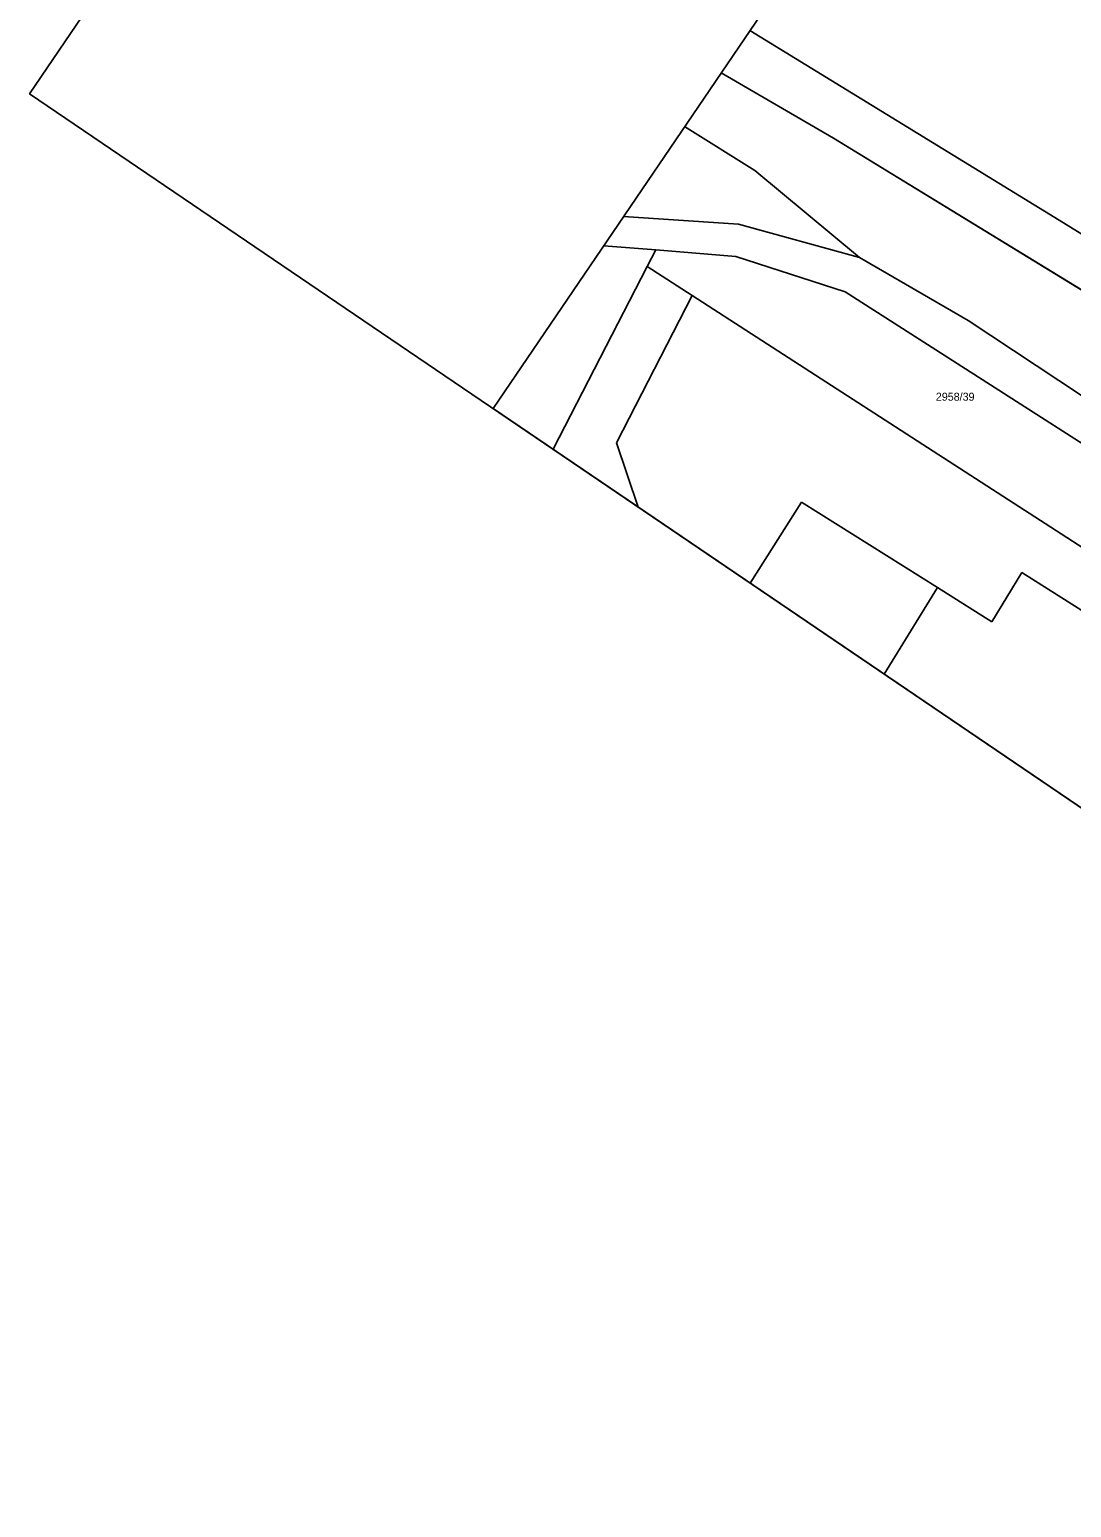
# Model space of a CAD drawing. Extents: x -621058 to -620110, y -1122807 to -1122030.
# Drawn here: x -621058.1 to -620862.9, y -1122540.7 to -1122263.7 of the extents above; entities that cross this region are included whole.
import ezdxf

# ---------------------------------------------------------------- set-up
doc = ezdxf.new("R2010")
doc.units = 0
for name, color, linetype in [('RÁMY', 7, 'Continuous'), ('Vrstva 53', 7, 'Continuous'), ('Vrstva 55', 7, 'Continuous'), ('Vrstva 56', 7, 'Continuous'), ('Vrstva 57', 7, 'Continuous')]:
    doc.layers.add(name, color=color, linetype=linetype)

msp = doc.modelspace()

# ---------------------------------------------------------------- linework, layer by layer
at = {"layer": 'RÁMY'}
for points in [[(-620974.7, -1122152.91), (-620192.94, -1122683.83), (-620276.37, -1122806.68), (-621058.13, -1122275.76)], [(-620887.83, -1122211.9), (-620192.94, -1122683.83), (-620276.37, -1122806.68), (-620971.26, -1122334.75)]]:
    msp.add_lwpolyline(points, close=True, dxfattribs=at)
at = {"layer": 'Vrstva 53'}
for p, q in [((-620928.55, -1122271.85), (-620907.48, -1122284.08)), ((-620922.25, -1122290.14), (-620935.39, -1122281.92)), ((-620902.62, -1122306.44), (-620922.25, -1122290.14)), ((-620882.26, -1122318.28), (-620902.62, -1122306.44)), ((-620856.79, -1122335.14), (-620882.26, -1122318.28))]:
    msp.add_line(p, q, dxfattribs=at)
msp.add_lwpolyline([(-620907.48, -1122284.08), (-620847.72, -1122320.67), (-620856.79, -1122335.14)], dxfattribs=at)
at = {"layer": 'Vrstva 55'}
for p, q in [((-620923.17, -1122263.93), (-620866.03, -1122298.98)), ((-620928.55, -1122271.85), (-620907.48, -1122284.08)), ((-620935.39, -1122281.92), (-620922.25, -1122290.14)), ((-620907.48, -1122284.08), (-620847.72, -1122320.67)), ((-620922.25, -1122290.14), (-620902.62, -1122306.44)), ((-620946.82, -1122298.75), (-620925.27, -1122300.21)), ((-620866.03, -1122298.98), (-620688.16, -1122408.5)), ((-620925.27, -1122300.21), (-620902.62, -1122306.44)), ((-620950.55, -1122304.25), (-620940.78, -1122305.04)), ((-620940.78, -1122305.04), (-620942.38, -1122308.15)), ((-620940.78, -1122305.04), (-620925.79, -1122306.26)), ((-620905.33, -1122312.86), (-620925.79, -1122306.26)), ((-620902.62, -1122306.44), (-620882.26, -1122318.28)), ((-620960, -1122342.4), (-620942.38, -1122308.15)), ((-620942.38, -1122308.15), (-620933.94, -1122313.6)), ((-620894.54, -1122319.77), (-620905.33, -1122312.86)), ((-620933.94, -1122313.6), (-620948.13, -1122341.18)), ((-620848.87, -1122368.55), (-620933.94, -1122313.6)), ((-620856.79, -1122335.14), (-620882.26, -1122318.28)), ((-620894.54, -1122319.77), (-620853.22, -1122346.25)), ((-620948.13, -1122341.18), (-620944.07, -1122353.22)), ((-620923.07, -1122367.48), (-620913.46, -1122352.29)), ((-620887.98, -1122368.3), (-620913.46, -1122352.29)), ((-620872.17, -1122365.51), (-620877.81, -1122374.71)), ((-620872.17, -1122365.51), (-620820.94, -1122397.9)), ((-620887.98, -1122368.3), (-620877.81, -1122374.71))]:
    msp.add_line(p, q, dxfattribs=at)
at = {"layer": 'Vrstva 56'}
msp.add_line((-620887.98, -1122368.3), (-620897.97, -1122384.52), dxfattribs=at)

# ---------------------------------------------------------------- texts
at = {"layer": 'Vrstva 57'}
msp.add_text('2958/39', height=1.5, dxfattribs=at).set_placement((-620888.31, -1122333.29))

doc.saveas('drawing.dxf')
